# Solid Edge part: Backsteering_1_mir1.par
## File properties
Author: KULL
Template: Iso Metric Part.par
Last saved by: KULL
Revision: 2
Application: Solid Edge
Accuracy: 0,990
Username: KULL
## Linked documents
Backsteering_1.par
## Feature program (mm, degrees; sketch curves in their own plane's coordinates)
part copy "CopiedPart_1"
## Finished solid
Body 1: solid body, 239 faces, 533 edges, 296 vertices.
  Faces by surface: cylinder 104, torus 63, plane 40, blend 27, sphere 5
  Edges by curve: circle 280, line 198, ellipse 28, intersection 26, curve on surface 1
Bounding box of the edges (mm; curved faces can reach further): 28.000 x 37.345 x 39.295, from (-5, -22.1032, -19.6474) to (23, 15.242, 19.6474).
Cylindrical faces by radius (mm): R0.2 x28, R0.8 x37, R1.3 x1, R1.8 x2, R2 x4, R3 x5, R4 x12, R5 x8, R6 x3, R8 x2, R9 x2
Toroidal faces (ring radius, tube radius in mm): R1 r0.2 x2, R1 r0.8 x2, R1.2 r0.8 x2, R1.5 r0.2 x2, R1.6 r0.2 x2, R1.7 r0.4 x1, R2.2 r0.8 x4, R2.4 r0.4 x2, R3.2 r0.2 x4, R3.2 r0.8 x2, R4.2 r0.2 x12, R4.2 r0.8 x4, R4.8 r0.2 x4, R4.8 r0.8 x4, R5.2 r0.8 x4, R5.8 r0.8 x4, R8.2 r0.2 x2, R8.8 r0.2 x2, R8.8 r0.8 x2, R9.8 r0.8 x2
Spherical faces by radius (mm): R0.8 x2, R3 x1, R4 x2
Planar faces by outward normal: +x 3, +y 5, +z 2, -x 4, -y 5, -z 2, oblique 19
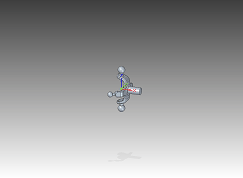
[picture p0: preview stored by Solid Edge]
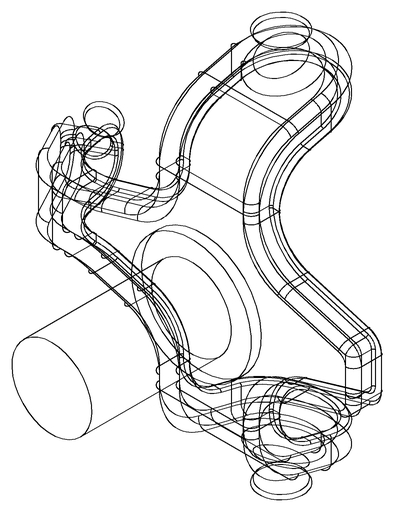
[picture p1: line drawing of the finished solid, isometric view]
